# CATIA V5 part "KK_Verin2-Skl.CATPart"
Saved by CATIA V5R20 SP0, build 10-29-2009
Part number: Verin2-Skl
Bounding box of the stored display mesh (mm): x 20 to 49.705, y 61.671 to 86.772, z 0 to 100
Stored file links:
  G:\Khaled_CFAO_2011\ST2M\ST2M_GR1\msallin\Khaled\Version_Finale\KK_Verin2-Skl.CATPart
  C:\Users\Mathieu\Desktop\Think Motion\JOUG-MELEE2.CATProduct
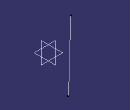
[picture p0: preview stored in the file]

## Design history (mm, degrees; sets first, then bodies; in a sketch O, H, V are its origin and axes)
Set1
  Point1: linked copy from another document
  Point2: linked copy from another document
Set2
  Line1: type PtPt, FirstPoint Point1, SecondPoint Point2
Body1 (main body)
